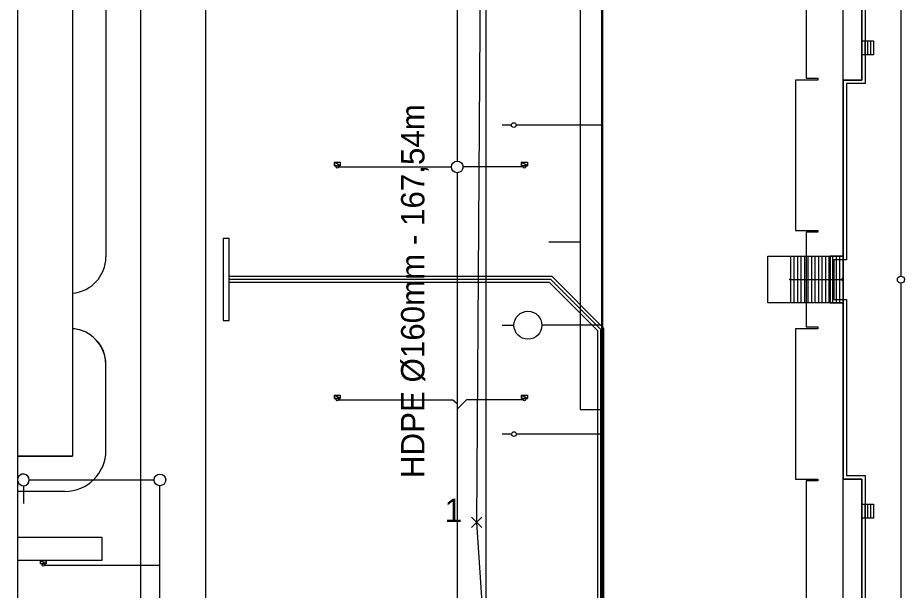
# Model space of a CAD drawing. Extents: x -263964 to -263544, y -1242317 to -1242020.
# Drawn here: x -263964.1 to -263888.2, y -1242190.9 to -1242142 of the extents above; entities that cross this region are included whole.
import ezdxf

# ---------------------------------------------------------------- set-up
doc = ezdxf.new("R2010")
doc.units = 0
for name, color, linetype in [('KFA_KOORDINACNA_SITUACIA_DSP_SEDA', 7, 'Continuous'), ('KFA_SO_50-2_POZIARNY_VODOVOD_BODY', 7, 'Continuous'), ('KFA_SO_50-2_POZIARNY_VODOVOD_TRASA', 7, 'Continuous'), ('POPIS', 7, 'Continuous'), ('RAM_NA_TLAC_A3_1-100', 7, 'Continuous')]:
    doc.layers.add(name, color=color, linetype=linetype)

msp = doc.modelspace()

# ---------------------------------------------------------------- linework, layer by layer
at = {"layer": 'KFA_KOORDINACNA_SITUACIA_DSP_SEDA'}
for p, q in [((-263959.468, -1242059.534), (-263959.468, -1242179.482)), ((-263924.143, -1242082.64), (-263924.143, -1242185.14)), ((-263948.093, -1242087.901), (-263948.093, -1242241.458)), ((-263953.617, -1242244.458), (-263953.617, -1242093.307)), ((-263926.593, -1242107.902), (-263926.593, -1242154.252)), ((-263926.593, -1242107.902), (-263926.593, -1242154.252)), ((-263888.673, -1242108.177), (-263888.673, -1242164.087)), ((-263896.768, -1242125.432), (-263896.768, -1242147.182)), ((-263956.618, -1242127.418), (-263956.618, -1242162.449)), ((-263914.218, -1242196.332), (-263914.218, -1242132.432)), ((-263892.018, -1242143.983), (-263891.018, -1242143.983)), ((-263891.768, -1242143.983), (-263891.768, -1242145.181)), ((-263891.518, -1242143.983), (-263891.518, -1242145.181)), ((-263891.268, -1242143.983), (-263891.268, -1242145.181)), ((-263891.018, -1242143.983), (-263891.018, -1242145.181)), ((-263891.018, -1242145.181), (-263892.018, -1242145.181)), ((-263895.768, -1242147.332), (-263897.693, -1242147.332)), ((-263897.693, -1242147.332), (-263897.693, -1242160.182)), ((-263896.768, -1242147.182), (-263895.768, -1242147.182)), ((-263895.768, -1242147.182), (-263895.768, -1242147.332)), ((-263921.957, -1242151.182), (-263922.757, -1242151.182)), ((-263917.093, -1242151.182), (-263921.557, -1242151.182)), ((-263914.143, -1242151.182), (-263917.093, -1242151.182)), ((-263937.093, -1242154.652), (-263937.093, -1242154.362)), ((-263937.093, -1242154.362), (-263936.593, -1242154.362)), ((-263936.593, -1242154.652), (-263937.093, -1242154.362)), ((-263936.593, -1242154.652), (-263937.093, -1242154.362)), ((-263937.093, -1242154.362), (-263937.093, -1242154.652)), ((-263936.593, -1242154.652), (-263937.093, -1242154.652)), ((-263937.093, -1242154.652), (-263936.593, -1242154.652)), ((-263936.743, -1242154.752), (-263927.093, -1242154.752)), ((-263936.593, -1242154.362), (-263936.593, -1242154.652)), ((-263920.944, -1242154.752), (-263926.093, -1242154.752)), ((-263921.093, -1242154.652), (-263921.093, -1242154.362)), ((-263921.093, -1242154.362), (-263920.593, -1242154.362)), ((-263920.593, -1242154.652), (-263921.093, -1242154.362)), ((-263920.593, -1242154.652), (-263921.093, -1242154.362)), ((-263921.093, -1242154.362), (-263921.093, -1242154.652)), ((-263920.593, -1242154.652), (-263921.093, -1242154.652)), ((-263921.093, -1242154.652), (-263920.593, -1242154.652)), ((-263920.593, -1242154.362), (-263920.593, -1242154.652)), ((-263926.593, -1242155.252), (-263926.593, -1242204.252)), ((-263897.693, -1242160.182), (-263895.768, -1242160.182)), ((-263895.768, -1242160.332), (-263896.768, -1242160.332)), ((-263896.768, -1242160.332), (-263896.768, -1242168.432)), ((-263895.768, -1242160.182), (-263895.768, -1242160.332)), ((-263916.093, -1242161.182), (-263918.763, -1242161.182)), ((-263898.118, -1242162.382), (-263898.118, -1242166.382)), ((-263897.818, -1242162.382), (-263897.818, -1242166.382)), ((-263897.518, -1242162.382), (-263897.518, -1242166.382)), ((-263897.218, -1242162.382), (-263897.218, -1242166.382)), ((-263896.918, -1242162.382), (-263896.918, -1242166.382)), ((-263896.618, -1242162.382), (-263896.618, -1242166.382)), ((-263896.318, -1242162.382), (-263896.318, -1242166.382)), ((-263896.018, -1242162.382), (-263896.018, -1242166.382)), ((-263895.718, -1242162.382), (-263895.718, -1242166.382)), ((-263895.418, -1242162.382), (-263895.418, -1242166.382)), ((-263895.118, -1242162.382), (-263895.118, -1242166.382)), ((-263894.818, -1242162.382), (-263894.818, -1242166.382)), ((-263894.518, -1242162.382), (-263894.518, -1242166.382)), ((-263894.218, -1242162.382), (-263894.218, -1242166.382)), ((-263893.918, -1242162.382), (-263893.918, -1242166.382)), ((-263893.618, -1242162.382), (-263893.618, -1242166.382)), ((-263918.489, -1242164.132), (-263946.093, -1242164.132)), ((-263918.593, -1242164.382), (-263946.093, -1242164.382)), ((-263918.696, -1242164.632), (-263946.093, -1242164.632)), ((-263898.118, -1242164.382), (-263893.618, -1242164.382)), ((-263893.618, -1242164.382), (-263893.721, -1242164.274)), ((-263893.618, -1242164.382), (-263893.721, -1242164.491)), ((-263888.673, -1242164.687), (-263888.673, -1242220.396)), ((-263959.468, -1242165.549), (-263959.468, -1242165.549)), ((-263959.467, -1242168.582), (-263959.467, -1242168.582)), ((-263922.745, -1242168.282), (-263921.745, -1242168.282)), ((-263914.143, -1242168.282), (-263919.355, -1242168.282)), ((-263895.768, -1242168.582), (-263897.693, -1242168.582)), ((-263897.693, -1242168.582), (-263897.693, -1242181.432)), ((-263896.768, -1242168.432), (-263895.768, -1242168.432)), ((-263895.768, -1242168.432), (-263895.768, -1242168.582)), ((-263956.618, -1242178.982), (-263956.618, -1242171.645)), ((-263937.093, -1242174.553), (-263937.093, -1242174.263)), ((-263937.093, -1242174.263), (-263936.593, -1242174.263)), ((-263936.593, -1242174.553), (-263937.093, -1242174.263)), ((-263936.593, -1242174.553), (-263937.093, -1242174.263)), ((-263937.093, -1242174.263), (-263937.093, -1242174.553)), ((-263936.593, -1242174.553), (-263937.093, -1242174.553)), ((-263937.093, -1242174.553), (-263936.593, -1242174.553)), ((-263936.743, -1242174.653), (-263926.953, -1242174.653)), ((-263936.593, -1242174.263), (-263936.593, -1242174.553)), ((-263926.953, -1242174.653), (-263926.593, -1242174.978)), ((-263925.798, -1242174.653), (-263926.593, -1242175.448)), ((-263920.944, -1242174.653), (-263925.798, -1242174.653)), ((-263921.093, -1242174.553), (-263921.093, -1242174.263)), ((-263921.093, -1242174.263), (-263920.593, -1242174.263)), ((-263920.593, -1242174.553), (-263921.093, -1242174.263)), ((-263920.593, -1242174.553), (-263921.093, -1242174.263)), ((-263921.093, -1242174.263), (-263921.093, -1242174.553)), ((-263920.593, -1242174.553), (-263921.093, -1242174.553)), ((-263921.093, -1242174.553), (-263920.593, -1242174.553)), ((-263920.593, -1242174.263), (-263920.593, -1242174.553)), ((-263921.938, -1242177.582), (-263922.738, -1242177.582)), ((-263915.293, -1242177.582), (-263921.538, -1242177.582)), ((-263914.143, -1242177.582), (-263915.293, -1242177.582)), ((-263956.618, -1242178.982), (-263956.618, -1242178.982)), ((-263959.468, -1242179.482), (-263964.149, -1242179.482)), ((-263964.149, -1242179.482), (-263959.468, -1242179.482)), ((-263959.468, -1242179.482), (-263964.149, -1242179.482)), ((-263963.161, -1242181.5), (-263952.5, -1242181.5)), ((-263897.693, -1242181.432), (-263895.768, -1242181.432)), ((-263895.768, -1242181.582), (-263896.768, -1242181.582)), ((-263896.768, -1242181.582), (-263896.768, -1242203.332)), ((-263895.768, -1242181.432), (-263895.768, -1242181.582)), ((-263963.661, -1242182), (-263963.661, -1242183.528)), ((-263952, -1242222.527), (-263952, -1242182)), ((-263960.118, -1242182.482), (-263964.149, -1242182.482)), ((-263892.018, -1242183.583), (-263891.018, -1242183.583)), ((-263891.768, -1242183.583), (-263891.768, -1242184.781)), ((-263891.518, -1242183.583), (-263891.518, -1242184.781)), ((-263891.268, -1242183.583), (-263891.268, -1242184.781)), ((-263891.018, -1242183.583), (-263891.018, -1242184.781)), ((-263924.143, -1242185.14), (-263924.143, -1242250.14)), ((-263891.018, -1242184.781), (-263892.018, -1242184.781)), ((-263964.149, -1242188.382), (-263964.149, -1242186.382)), ((-263964.149, -1242186.382), (-263956.968, -1242186.382)), ((-263956.968, -1242186.382), (-263956.968, -1242188.382)), ((-263956.968, -1242188.382), (-263964.149, -1242188.382)), ((-263962.218, -1242188.382), (-263961.718, -1242188.382)), ((-263962.218, -1242188.672), (-263962.218, -1242188.382)), ((-263962.218, -1242188.382), (-263961.718, -1242188.672)), ((-263962.218, -1242188.382), (-263961.718, -1242188.672)), ((-263961.718, -1242188.382), (-263962.218, -1242188.382)), ((-263961.718, -1242188.382), (-263961.718, -1242188.672)), ((-263961.718, -1242188.672), (-263961.718, -1242188.382)), ((-263961.718, -1242188.672), (-263962.218, -1242188.672)), ((-263961.868, -1242188.772), (-263952, -1242188.772))]:
    msp.add_line(p, q, dxfattribs=at)
for points in [[(-263794.893, -1242227.382), (-263808.968, -1242241.457), (-263894.968, -1242241.457), (-263909.043, -1242227.382), (-263909.043, -1242196.333), (-263914.143, -1242196.333), (-263914.143, -1242132.433), (-263909.043, -1242132.433), (-263909.043, -1242101.382), (-263894.968, -1242087.307), (-263808.968, -1242087.307), (-263794.893, -1242101.382), (-263794.893, -1242227.382)], [(-263816.02, -1242224.432), (-263887.916, -1242224.432), (-263888.26, -1242224.088), (-263889.254, -1242226.488), (-263890.391, -1242225.351), (-263894.351, -1242229.311), (-263896.896, -1242226.765), (-263892.937, -1242222.806), (-263894.073, -1242221.669), (-263891.673, -1242220.675), (-263892.018, -1242220.33), (-263892.018, -1242181.432), (-263893.618, -1242181.432), (-263893.618, -1242147.332), (-263892.018, -1242147.332), (-263892.018, -1242108.434)], [(-263918.489, -1242164.132), (-263914.1, -1242168.521), (-263914.1, -1242199.486), (-263910.004, -1242203.582), (-263891.768, -1242203.582)], [(-263918.696, -1242164.632), (-263914.6, -1242168.728), (-263914.6, -1242199.693), (-263910.211, -1242204.082), (-263891.768, -1242204.082)], [(-263918.593, -1242164.382), (-263914.35, -1242168.625), (-263914.35, -1242199.59), (-263910.108, -1242203.832), (-263891.768, -1242203.832)], [(-263956.618, -1242178.982), (-263956.618, -1242171.626), (-263956.64, -1242171.257), (-263956.707, -1242170.894), (-263956.87, -1242170.411), (-263957.158, -1242169.893), (-263957.435, -1242169.549), (-263957.705, -1242169.291), (-263958.077, -1242169.024), (-263958.45, -1242168.829), (-263958.842, -1242168.69), (-263959.056, -1242168.638), (-263959.273, -1242168.601), (-263959.468, -1242168.582)]]:
    msp.add_lwpolyline(points, dxfattribs=at)
for points in [[(-263816.02, -1242224.432), (-263811.918, -1242220.33), (-263811.918, -1242108.434), (-263816.02, -1242104.332), (-263887.916, -1242104.332), (-263892.018, -1242108.434), (-263892.018, -1242147.332), (-263893.618, -1242147.332), (-263893.618, -1242162.382), (-263894.718, -1242162.382), (-263894.718, -1242166.382), (-263893.618, -1242166.382), (-263893.618, -1242181.432), (-263892.018, -1242181.432), (-263892.018, -1242220.33), (-263887.916, -1242224.432)], [(-263816.144, -1242224.132), (-263812.218, -1242220.206), (-263812.218, -1242108.558), (-263816.144, -1242104.632), (-263887.792, -1242104.632), (-263891.718, -1242108.558), (-263891.718, -1242147.632), (-263893.318, -1242147.632), (-263893.318, -1242162.682), (-263894.418, -1242162.682), (-263894.418, -1242166.082), (-263893.318, -1242166.082), (-263893.318, -1242181.132), (-263891.718, -1242181.132), (-263891.718, -1242220.206), (-263887.792, -1242224.132)], [(-263893.618, -1242118.282), (-263916.093, -1242118.282), (-263916.093, -1242175.482), (-263914.293, -1242175.482), (-263914.293, -1242210.482), (-263893.618, -1242210.482), (-263893.618, -1242166.382), (-263900.043, -1242166.382), (-263900.043, -1242162.382), (-263893.618, -1242162.382)], [(-263946.093, -1242167.882), (-263946.093, -1242160.882), (-263946.593, -1242160.882), (-263946.593, -1242167.882)]]:
    msp.add_lwpolyline(points, close=True, dxfattribs=at)
for centre, radius in [((-263921.757, -1242151.182), 0.2), ((-263926.593, -1242154.752), 0.5), ((-263936.843, -1242154.752), 0.1), ((-263920.844, -1242154.752), 0.1), ((-263888.673, -1242164.387), 0.3), ((-263898.118, -1242164.382), 0.05), ((-263920.55, -1242168.282), 1.195), ((-263936.843, -1242174.653), 0.1), ((-263920.844, -1242174.653), 0.1), ((-263921.738, -1242177.582), 0.2), ((-263952, -1242181.5), 0.5), ((-263961.968, -1242188.772), 0.1)]:
    msp.add_circle(centre, radius, dxfattribs=at)
for centre, radius, start, end in [((-263959.738, -1242162.441), 3.12, 274.96374, 359.8482), ((-263959.668, -1242171.626), 3.05, 359.64411, 86.21555), ((-263960.118, -1242178.982), 3.5, 270, 0), ((-263963.661, -1242181.5), 0.5, 192.6281, 167.3719)]:
    msp.add_arc(centre, radius, start, end, dxfattribs=at)
at = {"layer": 'KFA_SO_50-2_POZIARNY_VODOVOD_BODY'}
for p, q in [((-263925.373, -1242185.569), (-263924.489, -1242184.685)), ((-263924.489, -1242185.569), (-263925.373, -1242184.685)), ((-263924.931, -1242185.127), (-263924.931, -1242185.127))]:
    msp.add_line(p, q, dxfattribs=at)
at = {"layer": 'KFA_SO_50-2_POZIARNY_VODOVOD_TRASA'}
msp.add_lwpolyline([(-263924.931, -1242185.127), (-263924.146, -1242197.091), (-263924.296, -1242220.899), (-263924.1, -1242250.121), (-263913.986, -1242249.798), (-263886.91, -1242249.876), (-263867.714, -1242249.83), (-263837.257, -1242249.836), (-263828.162, -1242249.901), (-263787.99, -1242250.032), (-263788.202, -1242220.837), (-263788.195, -1242200.509), (-263788.092, -1242179.915), (-263788.062, -1242148.958), (-263787.919, -1242127.952), (-263787.952, -1242110.966), (-263788.129, -1242082.536), (-263828.429, -1242082.723), (-263836.783, -1242082.559), (-263867.306, -1242082.615), (-263886.71, -1242082.472), (-263924.08, -1242082.613), (-263924.644, -1242106.322), (-263924.479, -1242117.427)], close=True, dxfattribs=at)
at = {"layer": 'RAM_NA_TLAC_A3_1-100'}
msp.add_lwpolyline([(-263964.149, -1242020.359), (-263544.149, -1242020.359), (-263544.149, -1242317.359), (-263964.149, -1242317.359)], close=True, dxfattribs=at)

# ---------------------------------------------------------------- texts
at = {"layer": 'KFA_SO_50-2_POZIARNY_VODOVOD_BODY'}
msp.add_text('1', height=2, dxfattribs=at).set_placement((-263927.665, -1242185.108))
at = {"layer": 'POPIS'}
msp.add_text('HDPE Ø160mm - 167,54m', height=2, rotation=90, dxfattribs=at).set_placement((-263929.394, -1242181.349))

doc.saveas('drawing.dxf')
